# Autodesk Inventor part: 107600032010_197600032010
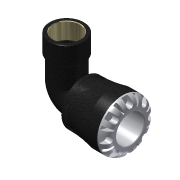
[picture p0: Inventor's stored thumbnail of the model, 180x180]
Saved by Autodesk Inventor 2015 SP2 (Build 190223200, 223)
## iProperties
Created: 2016-12
Part Number: 107600032010_197600032010
Material: PVC-Piping
Description: PLASSON 90° ELBOW WITH FEMALE INTEGRAL BRASS 32X1" SERIES 1
Document SubType Name: Modeling
Designer: KIM
Mass: 664.223 g
Surface Area: 733.008 cm^2
Volume: 474.445 cm^3
Density: 1.4 g/cm^3
Appearance: Black Cast
Author: KIM
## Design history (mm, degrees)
derived "1076.ipt"
feature "Solid1::1076.ipt"
tag "TaggingFeature1"
body "Solid1"
other parameters: "d1" = 22.26, "d2" = 32, "d4" = 58, "d8" = 51.04, "d13" = 7.2, "d14" = 7.2, "d15" = 0, "d17" = 360 deg, "d19" = 8 deg, "d20" = 0.64, "d21" = 0.64, "d22" = 8 deg, "d24" = 0, "d26" = 360 deg, "d33" = 5.8, "d51" = 0.58, "d54" = 11.2, "d55" = 7.04, "d57" = 14.112, "d58" = 0, "d74" = 0, "d78" = 53, "d82" = 0.64, "d115" = 360 deg, "d207" = 90 deg, "d228" = 9.52, "d248" = 3.18, "d270" = 73, "d281" = 4.54365, "d294" = 30.291, "d295" = 19, "d296" = 20.9, "d297" = 27.2619, "d299" = 35.44047, "d300" = 27.2619, "d301" = 0, "d302" = 0, "d306" = 1.96891, "d309" = 53.53, "d310" = 7.79977, "d312" = 15 deg, "d313" = 0.464, "d314" = 5.088, "d315" = 0.29, "d_" = 32, "E_" = 58, "l_" = 53, "A_" = 73, "l_2" = 19, "Rp_" = 30.291, "d9" = 9, "d11" = 58, "d298" = 39.3783
